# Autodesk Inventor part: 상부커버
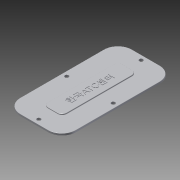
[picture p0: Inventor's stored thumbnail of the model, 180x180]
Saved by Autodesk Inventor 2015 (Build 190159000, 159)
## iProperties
Created: 2016-02
Part Number: 상부커버
Material: 알루미늄 6061
Document SubType Name: Modeling
Designer: mduedu
Density: 2.71 g/cm^3
Mass: 42.0587 g
Surface Area: 149.263 cm^2
Volume: 15.5198 cm^3
Appearance: 알루미늄 - 평지
Author: mduedu
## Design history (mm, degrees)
sketch "스케치1"
  geometry: L1 (30, 60)-(-30, 60); L2 (-30, 60)-(-30, -60); L3 (-30, -60)-(30, -60); L4 (30, -60)-(30, 60); L5 (30, 60)-(-30, -60); L6 (-30, 60)-(30, -60); 1 further point
  constraints: 12 end point, 2 midpoint, 2 parallel, 1 horizontal, 1 perpendicular
  dimensions: "d0" = 60 distance of L2.end L3.end; "d2" = 120 distance of L1.end L2.end
extrude "돌출1" new body sketch "스케치1" distance "d3" = 2; taper "d4" = 0 deg
fillet "모깎기1" dims "d5" = 15
sketch "스케치2"
  geometry: L1 (30, 45)-(30, -45) reference; L2 (15, -60)-(-15, -60) reference; L3 (-30, -45)-(-30, 45) reference; L4 (-15, 60)-(15, 60) reference; L5 (25, 45)-(25, -45); L6 (15, -55)-(-15, -55); L7 (-25, -45)-(-25, 45); L8 (-15, 55)-(15, 55); A1 r 15 centre (15, 45) between (30, 45) and (15, 60) reference; A2 r 15 centre (15, -45) between (15, -60) and (30, -45) reference; A3 r 15 centre (-15, -45) between (-30, -45) and (-15, -60) reference; A4 r 15 centre (-15, 45) between (-15, 60) and (-30, 45) reference; A5 r 10 centre (15, 45) between (25, 45) and (15, 55); A6 r 10 centre (15, -45) between (15, -55) and (25, -45); A7 r 10 centre (-15, -45) between (-25, -45) and (-15, -55); A8 r 10 centre (-15, 45) between (-15, 55) and (-25, 45); 4 further points
  constraints: 8 end point, 8 point on circle, 4 centre point, 4 midpoint, 7 other
  dimensions: "d8" = 5 distance between parallel lines of L7 L3
hole "구멍1" sketch "스케치2" at (0, 55), (25, 0), (0, -55), (-25, 0) diameter "d9" = 4; stored, may be unused: countersink angle "d13" = 90 deg, drill point angle "d15" = 118 deg; dims "d10" = 6, "d11" = 4, "d12" = 2, "d14" = 8
sketch "스케치3"
  geometry: L1 (10, -40)-(-10, -40); L2 (-10, -40)-(-10, 40); L3 (-10, 40)-(10, 40); L4 (10, 40)-(10, -40); L5 (10, -40)-(-10, 40); L6 (-10, -40)-(10, 40); 1 further point
  constraints: 12 end point, 2 midpoint, 2 parallel, 1 horizontal, 1 perpendicular
  dimensions: "d16" = 80 distance of L1.end L2.end; "d18" = 20 distance of L2.end L3.end
extrude "돌출2" join sketch "스케치3" distance "d19" = 1; taper "d20" = 0 deg
fillet "모깎기2" dims "d21" = 5
fillet "모깎기3" dims "d22" = 0.3
fillet "모깎기4" dims "d23" = 0.3
sketch "스케치4"
  geometry: 2 further points
  constraints: 1 coincident, 1 other
feature "엠보싱1" sketch "스케치4" dims "d0" = 60, "d2" = 120, "d8" = 5, "d24" = 0.5, "d25" = 0
node "솔리드1"
node "절단 모서리 투영1"
